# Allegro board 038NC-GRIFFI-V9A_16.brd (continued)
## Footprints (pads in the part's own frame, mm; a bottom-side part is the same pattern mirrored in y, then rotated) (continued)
PG_LTXDX_F_X1_HDVI_SL10_V3
  round 0.051 hole 2.489x2.21 unplated: (12.055,-220.342)
  round 0.508 hole 3.2 unplated: (13.055,-154.842)
  rect 1.016x1.016 hole 0.559: A1(17.684,-218.796)
  round 1.016 hole 0.559: A2(18.809,-217.796) A3(17.684,-216.796) A4(18.809,-215.796) A5(17.684,-214.796) A6(18.809,-213.796) A7(17.684,-212.796) A8(18.809,-211.796) A9(17.684,-210.796) A10(18.809,-209.796) A11(17.684,-208.796) A12(18.809,-207.796) A13(17.684,-206.796) A14(18.809,-205.796) A15(17.684,-204.796) A16(18.809,-203.796) A17(17.684,-202.796) A18(18.809,-201.796) A19(17.684,-200.796) A20(18.809,-199.796) A21(17.684,-198.796) A22(18.809,-197.796) A23(17.684,-196.796) A24(18.809,-195.796) A25(17.684,-194.796) A26(18.809,-193.796) A27(17.684,-192.796) A28(18.809,-191.796) A29(17.684,-190.796) A30(18.809,-189.796) A31(17.684,-188.796) A32(18.809,-187.796) A33(17.684,-186.796) A34(18.809,-185.796) A35(17.684,-184.796) A36(18.809,-183.796) A37(17.684,-182.796) A38(18.809,-181.796) A39(17.684,-180.796) A40(18.809,-179.796) A41(17.684,-178.796) A42(18.809,-177.796) A43(17.684,-176.796) A44(18.809,-175.796) A45(17.684,-174.796) A46(18.809,-173.796) A47(17.684,-172.796) A48(18.809,-171.796) A49(17.684,-170.796) A50(18.809,-169.796) A51(17.684,-168.796) A52(18.809,-167.796) A53(17.684,-166.796) A54(18.809,-165.796) A55(17.684,-164.796) A56(18.809,-163.796) A57(17.684,-162.796) A58(18.809,-161.796) A59(17.684,-160.796) A60(18.809,-159.796) A61(17.684,-158.796) B1(15.435,-218.796) B2(16.56,-217.796) B3(15.435,-216.796) B4(16.56,-215.796) B5(15.435,-214.796) B6(16.56,-213.796) B7(15.435,-212.796) B8(16.56,-211.796) B9(15.435,-210.796) B10(16.56,-209.796) B11(15.435,-208.796) B12(16.56,-207.796) B13(15.435,-206.796) B14(16.56,-205.796) B15(15.435,-204.796) B16(16.56,-203.796) B17(15.435,-202.796) B18(16.56,-201.796) B19(15.435,-200.796) B20(16.56,-199.796) B21(15.435,-198.796) B22(16.56,-197.796) B23(15.435,-196.796) B24(16.56,-195.796) B25(15.435,-194.796) B26(16.56,-193.796) B27(15.435,-192.796) B28(16.56,-191.796) B29(15.435,-190.796) B30(16.56,-189.796) B31(15.435,-188.796) B32(16.56,-187.796) B33(15.435,-186.796) B34(16.56,-185.796) B35(15.435,-184.796) B36(16.56,-183.796) B37(15.435,-182.796) B38(16.56,-181.796) B39(15.435,-180.796) B40(16.56,-179.796) B41(15.435,-178.796) B42(16.56,-177.796) B43(15.435,-176.796) B44(16.56,-175.796) B45(15.435,-174.796) B46(16.56,-173.796) B47(15.435,-172.796) B48(16.56,-171.796) B49(15.435,-170.796) B50(16.56,-169.796) B51(15.435,-168.796) B52(16.56,-167.796) B53(15.435,-166.796) B54(16.56,-165.796) B55(15.435,-164.796) B56(16.56,-163.796) B57(15.435,-162.796) B58(16.56,-161.796) B59(15.435,-160.796) B60(16.56,-159.796) B61(15.435,-158.796) B62(16.56,-157.796) C1(13.184,-218.796) C2(14.31,-217.796) C3(13.184,-216.796) C4(14.31,-215.796) C5(13.184,-214.796) C6(14.31,-213.796) C7(13.184,-212.796) C8(14.31,-211.796) C9(13.184,-210.796) C10(14.31,-209.796) C11(13.184,-208.796) C12(14.31,-207.796) C13(13.184,-206.796) C14(14.31,-205.796) C15(13.184,-204.796) C16(14.31,-203.796) C17(13.184,-202.796) C18(14.31,-201.796) C19(13.184,-200.796) C20(14.31,-199.796) C21(13.184,-198.796) C22(14.31,-197.796) C23(13.184,-196.796) C24(14.31,-195.796) C25(13.184,-194.796) C26(14.31,-193.796) C27(13.184,-192.796) C28(14.31,-191.796) C29(13.184,-190.796) C30(14.31,-189.796) C31(13.184,-188.796) C32(14.31,-187.796) C33(13.184,-186.796) C34(14.31,-185.796) C35(13.184,-184.796) C36(14.31,-183.796) C37(13.184,-182.796) C38(14.31,-181.796) C39(13.184,-180.796) C40(14.31,-179.796) C41(13.184,-178.796) C42(14.31,-177.796) C43(13.184,-176.796) C44(14.31,-175.796) C45(13.184,-174.796) C46(14.31,-173.796) C47(13.184,-172.796) C48(14.31,-171.796) C49(13.184,-170.796) C50(14.31,-169.796) C51(13.184,-168.796) C52(14.31,-167.796) C53(13.184,-166.796) C54(14.31,-165.796) C55(13.184,-164.796) C56(14.31,-163.796) C57(13.184,-162.796) C58(14.31,-161.796) C59(13.184,-160.796) C60(14.31,-159.796) C61(13.184,-158.796) C62(14.31,-157.796) D1(10.934,-218.796) D2(12.059,-217.796) D3(10.934,-216.796) D4(12.059,-215.796) D5(10.934,-214.796) D6(12.059,-213.796) D7(10.934,-212.796) D8(12.059,-211.796) D9(10.934,-210.796) D10(12.059,-209.796) D11(10.934,-208.796) D12(12.059,-207.796) D13(10.934,-206.796) D14(12.059,-205.796) D15(10.934,-204.796) D16(12.059,-203.796) D17(10.934,-202.796) D18(12.059,-201.796) D19(10.934,-200.796) D20(12.059,-199.796) D21(10.934,-198.796) D22(12.059,-197.796) D23(10.934,-196.796) D24(12.059,-195.796) D25(10.934,-194.796) D26(12.059,-193.796) D27(10.934,-192.796) D28(12.059,-191.796) D29(10.934,-190.796) D30(12.059,-189.796) D31(10.934,-188.796) D32(12.059,-187.796) D33(10.934,-186.796) D34(12.059,-185.796) D35(10.934,-184.796) D36(12.059,-183.796) D37(10.934,-182.796) D38(12.059,-181.796) D39(10.934,-180.796) D40(12.059,-179.796) D41(10.934,-178.796) D42(12.059,-177.796) D43(10.934,-176.796) D44(12.059,-175.796) D45(10.934,-174.796) D46(12.059,-173.796) D47(10.934,-172.796) D48(12.059,-171.796) D49(10.934,-170.796) D50(12.059,-169.796) D51(10.934,-168.796) D52(12.059,-167.796) D53(10.934,-166.796) D54(12.059,-165.796) D55(10.934,-164.796) D56(12.059,-163.796) D57(10.934,-162.796) D58(12.059,-161.796) D59(10.934,-160.796) D60(12.059,-159.796) D61(10.934,-158.796) E1(8.685,-218.796) E2(9.809,-217.796) E3(8.685,-216.796) E4(9.809,-215.796) E5(8.685,-214.796) E6(9.809,-213.796) E7(8.685,-212.796) E8(9.809,-211.796) E9(8.685,-210.796) E10(9.809,-209.796) E11(8.685,-208.796) E12(9.809,-207.796) E13(8.685,-206.796) E14(9.809,-205.796) E15(8.685,-204.796) E16(9.809,-203.796) E17(8.685,-202.796) E18(9.809,-201.796) E19(8.685,-200.796) E20(9.809,-199.796) E21(8.685,-198.796) E22(9.809,-197.796) E23(8.685,-196.796) E24(9.809,-195.796) E25(8.685,-194.796) E26(9.809,-193.796) E27(8.685,-192.796) E28(9.809,-191.796) E29(8.685,-190.796) E30(9.809,-189.796) E31(8.685,-188.796) E32(9.809,-187.796) E33(8.685,-186.796) E34(9.809,-185.796) E35(8.685,-184.796) E36(9.809,-183.796) E37(8.685,-182.796) E38(9.809,-181.796) E39(8.685,-180.796) E40(9.809,-179.796) E41(8.685,-178.796) E42(9.809,-177.796) E43(8.685,-176.796) E44(9.809,-175.796) E45(8.685,-174.796) E46(9.809,-173.796) E47(8.685,-172.796) E48(9.809,-171.796) E49(8.685,-170.796) E50(9.809,-169.796) E51(8.685,-168.796) E52(9.809,-167.796) E53(8.685,-166.796) E54(9.809,-165.796) E55(8.685,-164.796) E56(9.809,-163.796) E57(8.685,-162.796) E58(9.809,-161.796) E59(8.685,-160.796) E60(9.809,-159.796) E61(8.685,-158.796) E62(9.809,-157.796) F1(6.435,-218.796) F2(7.56,-217.796) F3(6.435,-216.796) F4(7.56,-215.796) F5(6.435,-214.796) F6(7.56,-213.796) F7(6.435,-212.796) F8(7.56,-211.796) F9(6.435,-210.796) F10(7.56,-209.796) F11(6.435,-208.796) F12(7.56,-207.796) F13(6.435,-206.796) F14(7.56,-205.796) F15(6.435,-204.796) F16(7.56,-203.796) F17(6.435,-202.796) F18(7.56,-201.796) F19(6.435,-200.796) F20(7.56,-199.796) F21(6.435,-198.796) F22(7.56,-197.796) F23(6.435,-196.796) F24(7.56,-195.796) F25(6.435,-194.796) F26(7.56,-193.796) F27(6.435,-192.796) F28(7.56,-191.796) F29(6.435,-190.796) F30(7.56,-189.796) F31(6.435,-188.796) F32(7.56,-187.796) F33(6.435,-186.796) F34(7.56,-185.796) F35(6.435,-184.796) F36(7.56,-183.796) F37(6.435,-182.796) F38(7.56,-181.796) F39(6.435,-180.796) F40(7.56,-179.796) F41(6.435,-178.796) F42(7.56,-177.796) F43(6.435,-176.796) F44(7.56,-175.796) F45(6.435,-174.796) F46(7.56,-173.796) F47(6.435,-172.796) F48(7.56,-171.796) F49(6.435,-170.796) F50(7.56,-169.796) F51(6.435,-168.796) F52(7.56,-167.796) F53(6.435,-166.796) F54(7.56,-165.796) F55(6.435,-164.796) F56(7.56,-163.796) F57(6.435,-162.796) F58(7.56,-161.796) F59(6.435,-160.796) F60(7.56,-159.796) F61(6.435,-158.796) F62(7.56,-157.796) G2(5.31,-217.796) G4(5.31,-215.796) G6(5.31,-213.796) G8(5.31,-211.796) G10(5.31,-209.796) G12(5.31,-207.796) G14(5.31,-205.796) G16(5.31,-203.796) G18(5.31,-201.796) G20(5.31,-199.796) G22(5.31,-197.796) G24(5.31,-195.796) G26(5.31,-193.796) G28(5.31,-191.796) G30(5.31,-189.796) G32(5.31,-187.796) G34(5.31,-185.796) G36(5.31,-183.796) G38(5.31,-181.796) G40(5.31,-179.796) G42(5.31,-177.796) G44(5.31,-175.796) G46(5.31,-173.796) G48(5.31,-171.796) G50(5.31,-169.796) G52(5.31,-167.796) G54(5.31,-165.796) G56(5.31,-163.796) G58(5.31,-161.796) G60(5.31,-159.796)
  custom 0.257x0.257 smd: Z5(19.934,-214.796) Z7(19.934,-212.796) Z9(19.934,-210.796) Z11(19.934,-208.796) Z13(19.934,-206.796) Z15(19.934,-204.796) Z17(19.934,-202.796) Z19(19.934,-200.796) Z21(19.934,-198.796) Z23(19.934,-196.796) Z25(19.934,-194.796) Z27(19.934,-192.796) Z29(19.934,-190.796) Z31(19.934,-188.796) Z33(19.934,-186.796) Z35(19.934,-184.796) Z37(19.934,-182.796) Z39(19.934,-180.796) Z41(19.934,-178.796) Z43(19.934,-176.796) Z45(19.934,-174.796) Z47(19.934,-172.796) Z49(19.934,-170.796) Z51(19.934,-168.796) Z53(19.934,-166.796) Z55(19.934,-164.796) Z57(19.934,-162.796) Z59(19.934,-160.796) Z61(19.934,-158.796)
PG_LTXDX_F_X1_HDVI_SL13_V3
  round 0.508 hole 3.2 unplated: (35.206,154.842)
  round 0.051 hole 2.489x2.21 unplated: (36.205,220.342)
  rect 1.016x1.016 hole 0.559: A1(30.576,218.796)
  round 1.016 hole 0.559: A2(29.451,217.796) A3(30.576,216.796) A4(29.451,215.796) A5(30.576,214.796) A6(29.451,213.796) A7(30.576,212.796) A8(29.451,211.796) A9(30.576,210.796) A10(29.451,209.796) A11(30.576,208.796) A12(29.451,207.796) A13(30.576,206.796) A14(29.451,205.796) A15(30.576,204.796) A16(29.451,203.796) A17(30.576,202.796) A18(29.451,201.796) A19(30.576,200.796) A20(29.451,199.796) A21(30.576,198.796) A22(29.451,197.796) A23(30.576,196.796) A24(29.451,195.796) A25(30.576,194.796) A26(29.451,193.796) A27(30.576,192.796) A28(29.451,191.796) A29(30.576,190.796) A30(29.451,189.796) A31(30.576,188.796) A32(29.451,187.796) A33(30.576,186.796) A34(29.451,185.796) A35(30.576,184.796) A36(29.451,183.796) A37(30.576,182.796) A38(29.451,181.796) A39(30.576,180.796) A40(29.451,179.796) A41(30.576,178.796) A42(29.451,177.796) A43(30.576,176.796) A44(29.451,175.796) A45(30.576,174.796) A46(29.451,173.796) A47(30.576,172.796) A48(29.451,171.796) A49(30.576,170.796) A50(29.451,169.796) A51(30.576,168.796) A52(29.451,167.796) A53(30.576,166.796) A54(29.451,165.796) A55(30.576,164.796) A56(29.451,163.796) A57(30.576,162.796) A58(29.451,161.796) A59(30.576,160.796) A60(29.451,159.796) A61(30.576,158.796) B1(32.825,218.796) B2(31.7,217.796) B3(32.825,216.796) B4(31.7,215.796) B5(32.825,214.796) B6(31.7,213.796) B7(32.825,212.796) B8(31.7,211.796) B9(32.825,210.796) B10(31.7,209.796) B11(32.825,208.796) B12(31.7,207.796) B13(32.825,206.796) B14(31.7,205.796) B15(32.825,204.796) B16(31.7,203.796) B17(32.825,202.796) B18(31.7,201.796) B19(32.825,200.796) B20(31.7,199.796) B21(32.825,198.796) B22(31.7,197.796) B23(32.825,196.796) B24(31.7,195.796) B25(32.825,194.796) B26(31.7,193.796) B27(32.825,192.796) B28(31.7,191.796) B29(32.825,190.796) B30(31.7,189.796) B31(32.825,188.796) B32(31.7,187.796) B33(32.825,186.796) B34(31.7,185.796) B35(32.825,184.796) B36(31.7,183.796) B37(32.825,182.796) B38(31.7,181.796) B39(32.825,180.796) B40(31.7,179.796) B41(32.825,178.796) B42(31.7,177.796) B43(32.825,176.796) B44(31.7,175.796) B45(32.825,174.796) B46(31.7,173.796) B47(32.825,172.796) B48(31.7,171.796) B49(32.825,170.796) B50(31.7,169.796) B51(32.825,168.796) B52(31.7,167.796) B53(32.825,166.796) B54(31.7,165.796) B55(32.825,164.796) B56(31.7,163.796) B57(32.825,162.796) B58(31.7,161.796) B59(32.825,160.796) B60(31.7,159.796) B61(32.825,158.796) B62(31.7,157.796) C1(35.076,218.796) C2(33.95,217.796) C3(35.076,216.796) C4(33.95,215.796) C5(35.076,214.796) C6(33.95,213.796) C7(35.076,212.796) C8(33.95,211.796) C9(35.076,210.796) C10(33.95,209.796) C11(35.076,208.796) C12(33.95,207.796) C13(35.076,206.796) C14(33.95,205.796) C15(35.076,204.796) C16(33.95,203.796) C17(35.076,202.796) C18(33.95,201.796) C19(35.076,200.796) C20(33.95,199.796) C21(35.076,198.796) C22(33.95,197.796) C23(35.076,196.796) C24(33.95,195.796) C25(35.076,194.796) C26(33.95,193.796) C27(35.076,192.796) C28(33.95,191.796) C29(35.076,190.796) C30(33.95,189.796) C31(35.076,188.796) C32(33.95,187.796) C33(35.076,186.796) C34(33.95,185.796) C35(35.076,184.796) C36(33.95,183.796) C37(35.076,182.796) C38(33.95,181.796) C39(35.076,180.796) C40(33.95,179.796) C41(35.076,178.796) C42(33.95,177.796) C43(35.076,176.796) C44(33.95,175.796) C45(35.076,174.796) C46(33.95,173.796) C47(35.076,172.796) C48(33.95,171.796) C49(35.076,170.796) C50(33.95,169.796) C51(35.076,168.796) C52(33.95,167.796) C53(35.076,166.796) C54(33.95,165.796) C55(35.076,164.796) C56(33.95,163.796) C57(35.076,162.796) C58(33.95,161.796) C59(35.076,160.796) C60(33.95,159.796) C61(35.076,158.796) C62(33.95,157.796) D1(37.326,218.796) D2(36.201,217.796) D3(37.326,216.796) D4(36.201,215.796) D5(37.326,214.796) D6(36.201,213.796) D7(37.326,212.796) D8(36.201,211.796) D9(37.326,210.796) D10(36.201,209.796) D11(37.326,208.796) D12(36.201,207.796) D13(37.326,206.796) D14(36.201,205.796) D15(37.326,204.796) D16(36.201,203.796) D17(37.326,202.796) D18(36.201,201.796) D19(37.326,200.796) D20(36.201,199.796) D21(37.326,198.796) D22(36.201,197.796) D23(37.326,196.796) D24(36.201,195.796) D25(37.326,194.796) D26(36.201,193.796) D27(37.326,192.796) D28(36.201,191.796) D29(37.326,190.796) D30(36.201,189.796) D31(37.326,188.796) D32(36.201,187.796) D33(37.326,186.796) D34(36.201,185.796) D35(37.326,184.796) D36(36.201,183.796) D37(37.326,182.796) D38(36.201,181.796) D39(37.326,180.796) D40(36.201,179.796) D41(37.326,178.796) D42(36.201,177.796) D43(37.326,176.796) D44(36.201,175.796) D45(37.326,174.796) D46(36.201,173.796) D47(37.326,172.796) D48(36.201,171.796) D49(37.326,170.796) D50(36.201,169.796) D51(37.326,168.796) D52(36.201,167.796) D53(37.326,166.796) D54(36.201,165.796) D55(37.326,164.796) D56(36.201,163.796) D57(37.326,162.796) D58(36.201,161.796) D59(37.326,160.796) D60(36.201,159.796) D61(37.326,158.796) E1(39.575,218.796) E2(38.451,217.796) E3(39.575,216.796) E4(38.451,215.796) E5(39.575,214.796) E6(38.451,213.796) E7(39.575,212.796) E8(38.451,211.796) E9(39.575,210.796) E10(38.451,209.796) E11(39.575,208.796) E12(38.451,207.796) E13(39.575,206.796) E14(38.451,205.796) E15(39.575,204.796) E16(38.451,203.796) E17(39.575,202.796) E18(38.451,201.796) E19(39.575,200.796) E20(38.451,199.796) E21(39.575,198.796) E22(38.451,197.796) E23(39.575,196.796) E24(38.451,195.796) E25(39.575,194.796) E26(38.451,193.796) E27(39.575,192.796) E28(38.451,191.796) E29(39.575,190.796) E30(38.451,189.796) E31(39.575,188.796) E32(38.451,187.796) E33(39.575,186.796) E34(38.451,185.796) E35(39.575,184.796) E36(38.451,183.796) E37(39.575,182.796) E38(38.451,181.796) E39(39.575,180.796) E40(38.451,179.796) E41(39.575,178.796) E42(38.451,177.796) E43(39.575,176.796) E44(38.451,175.796) E45(39.575,174.796) E46(38.451,173.796) E47(39.575,172.796) E48(38.451,171.796) E49(39.575,170.796) E50(38.451,169.796) E51(39.575,168.796) E52(38.451,167.796) E53(39.575,166.796) E54(38.451,165.796) E55(39.575,164.796) E56(38.451,163.796) E57(39.575,162.796) E58(38.451,161.796) E59(39.575,160.796) E60(38.451,159.796) E61(39.575,158.796) E62(38.451,157.796) F1(41.825,218.796) F2(40.7,217.796) F3(41.825,216.796) F4(40.7,215.796) F5(41.825,214.796) F6(40.7,213.796) F7(41.825,212.796) F8(40.7,211.796) F9(41.825,210.796) F10(40.7,209.796) F11(41.825,208.796) F12(40.7,207.796) F13(41.825,206.796) F14(40.7,205.796) F15(41.825,204.796) F16(40.7,203.796) F17(41.825,202.796) F18(40.7,201.796) F19(41.825,200.796) F20(40.7,199.796) F21(41.825,198.796) F22(40.7,197.796) F23(41.825,196.796) F24(40.7,195.796) F25(41.825,194.796) F26(40.7,193.796) F27(41.825,192.796) F28(40.7,191.796) F29(41.825,190.796) F30(40.7,189.796) F31(41.825,188.796) F32(40.7,187.796) F33(41.825,186.796) F34(40.7,185.796) F35(41.825,184.796) F36(40.7,183.796) F37(41.825,182.796) F38(40.7,181.796) F39(41.825,180.796) F40(40.7,179.796) F41(41.825,178.796) F42(40.7,177.796) F43(41.825,176.796) F44(40.7,175.796) F45(41.825,174.796) F46(40.7,173.796) F47(41.825,172.796) F48(40.7,171.796) F49(41.825,170.796) F50(40.7,169.796) F51(41.825,168.796) F52(40.7,167.796) F53(41.825,166.796) F54(40.7,165.796) F55(41.825,164.796) F56(40.7,163.796) F57(41.825,162.796) F58(40.7,161.796) F59(41.825,160.796) F60(40.7,159.796) F61(41.825,158.796) F62(40.7,157.796) G2(42.95,217.796) G4(42.95,215.796) G6(42.95,213.796) G8(42.95,211.796) G10(42.95,209.796) G12(42.95,207.796) G14(42.95,205.796) G16(42.95,203.796) G18(42.95,201.796) G20(42.95,199.796) G22(42.95,197.796) G24(42.95,195.796) G26(42.95,193.796) G28(42.95,191.796) G30(42.95,189.796) G32(42.95,187.796) G34(42.95,185.796) G36(42.95,183.796) G38(42.95,181.796) G40(42.95,179.796) G42(42.95,177.796) G44(42.95,175.796) G46(42.95,173.796) G48(42.95,171.796) G50(42.95,169.796) G52(42.95,167.796) G54(42.95,165.796) G56(42.95,163.796) G58(42.95,161.796) G60(42.95,159.796)
  custom 0.257x0.257 smd: Z5(28.326,214.796) Z7(28.326,212.796) Z9(28.326,210.796) Z11(28.326,208.796) Z13(28.326,206.796) Z15(28.326,204.796) Z17(28.326,202.796) Z19(28.326,200.796) Z21(28.326,198.796) Z23(28.326,196.796) Z25(28.326,194.796) Z27(28.326,192.796) Z29(28.326,190.796) Z31(28.326,188.796) Z33(28.326,186.796) Z35(28.326,184.796) Z37(28.326,182.796) Z39(28.326,180.796) Z41(28.326,178.796) Z43(28.326,176.796) Z45(28.326,174.796) Z47(28.326,172.796) Z49(28.326,170.796) Z51(28.326,168.796) Z53(28.326,166.796) Z55(28.326,164.796) Z57(28.326,162.796) Z59(28.326,160.796) Z61(28.326,158.796)
PG_LTXDX_F_X1_OUTLINE_FULL_V2
  round 0.508 hole 7.925 unplated: (-139.7,145.034)
  round 0.508 hole 11.125 unplated: (-139.7,-145.034) (139.7,145.034) (139.7,-145.034)
  round 0.508 hole 3.099 unplated: (-130.048,229.87)
  round 0.508 hole 3.404 unplated: (-130.048,-229.87)
  round 0.508 hole 4.674 unplated: (-128.27,187.325) (-128.27,60.325) (-128.27,-60.325) (-128.27,-187.325) (-120.65,229.87) (-120.65,144.78) (-120.65,-144.78) (-120.65,-229.87) (-72.39,229.87) (-72.39,144.78) (-72.39,-144.78) (-72.39,-229.87) (-24.13,229.87) (-24.13,144.78) (-24.13,-144.78) (-24.13,-229.87) (24.13,229.87) (24.13,144.78) (24.13,-144.78) (24.13,-229.87) (72.39,229.87) (72.39,144.78) (72.39,-144.78) (72.39,-229.87) (120.65,229.87) (120.65,144.78) (120.65,-144.78) (120.65,-229.87) (128.27,187.325) (128.27,60.325) (128.27,-60.325) (128.27,-187.325)
  round 0.508 hole 4.572x3.099 unplated: (130.048,229.87)
PG_LTXDX_F_X1_PG400ND_SL01_V3
  round 0.508 hole 3.2 unplated: (-109.574,154.842)
  round 0.051 hole 2.489x2.21 unplated: (-108.574,220.342)
  rect 1.016x1.016 smd: A1(-114.204,218.796)
  round 1.016 smd: A2(-115.329,217.796) A3(-114.204,216.796) A4(-115.329,215.796) B1(-111.955,218.796) B2(-113.08,217.796) B3(-111.955,216.796) B4(-113.08,215.796) B62(-113.08,157.796) C1(-109.704,218.796) C2(-110.83,217.796) C3(-109.704,216.796) C4(-110.83,215.796) C62(-110.83,157.796) D1(-107.454,218.796) D2(-108.579,217.796) D3(-107.454,216.796) D4(-108.579,215.796) E1(-105.205,218.796) E2(-106.329,217.796) E3(-105.205,216.796) E4(-106.329,215.796) E62(-106.329,157.796) F1(-102.955,218.796) F2(-104.08,217.796) F3(-102.955,216.796) F4(-104.08,215.796) F62(-104.08,157.796) G2(-101.83,217.796) G4(-101.83,215.796) G6(-101.83,213.796) G8(-101.83,211.796) G10(-101.83,209.796) G12(-101.83,207.796) G14(-101.83,205.796) G16(-101.83,203.796) G18(-101.83,201.796) G20(-101.83,199.796) G22(-101.83,197.796) G24(-101.83,195.796) G26(-101.83,193.796) G28(-101.83,191.796) G30(-101.83,189.796) G32(-101.83,187.796) G34(-101.83,185.796) G36(-101.83,183.796) G38(-101.83,181.796) G40(-101.83,179.796) G42(-101.83,177.796) G44(-101.83,175.796) G46(-101.83,173.796) G48(-101.83,171.796) G50(-101.83,169.796) G52(-101.83,167.796) G54(-101.83,165.796) G56(-101.83,163.796) G58(-101.83,161.796) G60(-101.83,159.796)
  custom 0.257x0.257 smd: A5(-114.204,214.796) A6(-115.329,213.796) A7(-114.204,212.796) A8(-115.329,211.796) A9(-114.204,210.796) A10(-115.329,209.796) A11(-114.204,208.796) A12(-115.329,207.796) A13(-114.204,206.796) A14(-115.329,205.796) A15(-114.204,204.796) A16(-115.329,203.796) A17(-114.204,202.796) A18(-115.329,201.796) A19(-114.204,200.796) A20(-115.329,199.796) A21(-114.204,198.796) A22(-115.329,197.796) A23(-114.204,196.796) A24(-115.329,195.796) A25(-114.204,194.796) A26(-115.329,193.796) A27(-114.204,192.796) A28(-115.329,191.796) A29(-114.204,190.796) A30(-115.329,189.796) A31(-114.204,188.796) A32(-115.329,187.796) A33(-114.204,186.796) A34(-115.329,185.796) A35(-114.204,184.796) A36(-115.329,183.796) A37(-114.204,182.796) A38(-115.329,181.796) A39(-114.204,180.796) A40(-115.329,179.796) A41(-114.204,178.796) A42(-115.329,177.796) A43(-114.204,176.796) A44(-115.329,175.796) A45(-114.204,174.796) A46(-115.329,173.796) A47(-114.204,172.796) A48(-115.329,171.796) A49(-114.204,170.796) A50(-115.329,169.796) A51(-114.204,168.796) A52(-115.329,167.796) A53(-114.204,166.796) A54(-115.329,165.796) A55(-114.204,164.796) A56(-115.329,163.796) A57(-114.204,162.796) A58(-115.329,161.796) A59(-114.204,160.796) A60(-115.329,159.796) A61(-114.204,158.796) B5(-111.955,214.796) B6(-113.08,213.796) B7(-111.955,212.796) B8(-113.08,211.796) B9(-111.955,210.796) B10(-113.08,209.796) B11(-111.955,208.796) B12(-113.08,207.796) B13(-111.955,206.796) B14(-113.08,205.796) B15(-111.955,204.796) B16(-113.08,203.796) B17(-111.955,202.796) B18(-113.08,201.796) B19(-111.955,200.796) B20(-113.08,199.796) B21(-111.955,198.796) B22(-113.08,197.796) B23(-111.955,196.796) B24(-113.08,195.796) B25(-111.955,194.796) B26(-113.08,193.796) B27(-111.955,192.796) B28(-113.08,191.796) B29(-111.955,190.796) B30(-113.08,189.796) B31(-111.955,188.796) B32(-113.08,187.796) B33(-111.955,186.796) B34(-113.08,185.796) B35(-111.955,184.796) B36(-113.08,183.796) B37(-111.955,182.796) B38(-113.08,181.796) B39(-111.955,180.796) B40(-113.08,179.796) B41(-111.955,178.796) B42(-113.08,177.796) B43(-111.955,176.796) B44(-113.08,175.796) B45(-111.955,174.796) B46(-113.08,173.796) B47(-111.955,172.796) B48(-113.08,171.796) B49(-111.955,170.796) B50(-113.08,169.796) B51(-111.955,168.796) B52(-113.08,167.796) B53(-111.955,166.796) B54(-113.08,165.796) B55(-111.955,164.796) B56(-113.08,163.796) B57(-111.955,162.796) B58(-113.08,161.796) B59(-111.955,160.796) B60(-113.08,159.796) B61(-111.955,158.796) C5(-109.704,214.796) C6(-110.83,213.796) C7(-109.704,212.796) C8(-110.83,211.796) C9(-109.704,210.796) C10(-110.83,209.796) C11(-109.704,208.796) C12(-110.83,207.796) C13(-109.704,206.796) C14(-110.83,205.796) C15(-109.704,204.796) C16(-110.83,203.796) C17(-109.704,202.796) C18(-110.83,201.796) C19(-109.704,200.796) C20(-110.83,199.796) C21(-109.704,198.796) C22(-110.83,197.796) C23(-109.704,196.796) C24(-110.83,195.796) C25(-109.704,194.796) C26(-110.83,193.796) C27(-109.704,192.796) C28(-110.83,191.796) C29(-109.704,190.796) C30(-110.83,189.796) C31(-109.704,188.796) C32(-110.83,187.796) C33(-109.704,186.796) C34(-110.83,185.796) C35(-109.704,184.796) C36(-110.83,183.796) C37(-109.704,182.796) C38(-110.83,181.796) C39(-109.704,180.796) C40(-110.83,179.796) C41(-109.704,178.796) C42(-110.83,177.796) C43(-109.704,176.796) C44(-110.83,175.796) C45(-109.704,174.796) C46(-110.83,173.796) C47(-109.704,172.796) C48(-110.83,171.796) C49(-109.704,170.796) C50(-110.83,169.796) C51(-109.704,168.796) C52(-110.83,167.796) C53(-109.704,166.796) C54(-110.83,165.796) C55(-109.704,164.796) C56(-110.83,163.796) C57(-109.704,162.796) C58(-110.83,161.796) C59(-109.704,160.796) C60(-110.83,159.796) C61(-109.704,158.796) D5(-107.454,214.796) D6(-108.579,213.796) D7(-107.454,212.796) D8(-108.579,211.796) D9(-107.454,210.796) D10(-108.579,209.796) D11(-107.454,208.796) D12(-108.579,207.796) D13(-107.454,206.796) D14(-108.579,205.796) D15(-107.454,204.796) D16(-108.579,203.796) D17(-107.454,202.796) D18(-108.579,201.796) D19(-107.454,200.796) D20(-108.579,199.796) D21(-107.454,198.796) D22(-108.579,197.796) D23(-107.454,196.796) D24(-108.579,195.796) D25(-107.454,194.796) D26(-108.579,193.796) D27(-107.454,192.796) D28(-108.579,191.796) D29(-107.454,190.796) D30(-108.579,189.796) D31(-107.454,188.796) D32(-108.579,187.796) D33(-107.454,186.796) D34(-108.579,185.796) D35(-107.454,184.796) D36(-108.579,183.796) D37(-107.454,182.796) D38(-108.579,181.796) D39(-107.454,180.796) D40(-108.579,179.796) D41(-107.454,178.796) D42(-108.579,177.796) D43(-107.454,176.796) D44(-108.579,175.796) D45(-107.454,174.796) D46(-108.579,173.796) D47(-107.454,172.796) D48(-108.579,171.796) D49(-107.454,170.796) D50(-108.579,169.796) D51(-107.454,168.796) D52(-108.579,167.796) D53(-107.454,166.796) D54(-108.579,165.796) D55(-107.454,164.796) D56(-108.579,163.796) D57(-107.454,162.796) D58(-108.579,161.796) D59(-107.454,160.796) D60(-108.579,159.796) D61(-107.454,158.796) E5(-105.205,214.796) E6(-106.329,213.796) E7(-105.205,212.796) E8(-106.329,211.796) E9(-105.205,210.796) E10(-106.329,209.796) E11(-105.205,208.796) E12(-106.329,207.796) E13(-105.205,206.796) E14(-106.329,205.796) E15(-105.205,204.796) E16(-106.329,203.796) E17(-105.205,202.796) E18(-106.329,201.796) E19(-105.205,200.796) E20(-106.329,199.796) E21(-105.205,198.796) E22(-106.329,197.796) E23(-105.205,196.796) E24(-106.329,195.796) E25(-105.205,194.796) E26(-106.329,193.796) E27(-105.205,192.796) E28(-106.329,191.796) E29(-105.205,190.796) E30(-106.329,189.796) E31(-105.205,188.796) E32(-106.329,187.796) E33(-105.205,186.796) E34(-106.329,185.796) E35(-105.205,184.796) E36(-106.329,183.796) E37(-105.205,182.796) E38(-106.329,181.796) E39(-105.205,180.796) E40(-106.329,179.796) E41(-105.205,178.796) E42(-106.329,177.796) E43(-105.205,176.796) E44(-106.329,175.796) E45(-105.205,174.796) E46(-106.329,173.796) E47(-105.205,172.796) E48(-106.329,171.796) E49(-105.205,170.796) E50(-106.329,169.796) E51(-105.205,168.796) E52(-106.329,167.796) E53(-105.205,166.796) E54(-106.329,165.796) E55(-105.205,164.796) E56(-106.329,163.796) E57(-105.205,162.796) E58(-106.329,161.796) E59(-105.205,160.796) E60(-106.329,159.796) E61(-105.205,158.796) F5(-102.955,214.796) F6(-104.08,213.796) F7(-102.955,212.796) F8(-104.08,211.796) F9(-102.955,210.796) F10(-104.08,209.796) F11(-102.955,208.796) F12(-104.08,207.796) F13(-102.955,206.796) F14(-104.08,205.796) F15(-102.955,204.796) F16(-104.08,203.796) F17(-102.955,202.796) F18(-104.08,201.796) F19(-102.955,200.796) F20(-104.08,199.796) F21(-102.955,198.796) F22(-104.08,197.796) F23(-102.955,196.796) F24(-104.08,195.796) F25(-102.955,194.796) F26(-104.08,193.796) F27(-102.955,192.796) F28(-104.08,191.796) F29(-102.955,190.796) F30(-104.08,189.796) F31(-102.955,188.796) F32(-104.08,187.796) F33(-102.955,186.796) F34(-104.08,185.796) F35(-102.955,184.796) F36(-104.08,183.796) F37(-102.955,182.796) F38(-104.08,181.796) F39(-102.955,180.796) F40(-104.08,179.796) F41(-102.955,178.796) F42(-104.08,177.796) F43(-102.955,176.796) F44(-104.08,175.796) F45(-102.955,174.796) F46(-104.08,173.796) F47(-102.955,172.796) F48(-104.08,171.796) F49(-102.955,170.796) F50(-104.08,169.796) F51(-102.955,168.796) F52(-104.08,167.796) F53(-102.955,166.796) F54(-104.08,165.796) F55(-102.955,164.796) F56(-104.08,163.796) F57(-102.955,162.796) F58(-104.08,161.796) F59(-102.955,160.796) F60(-104.08,159.796) F61(-102.955,158.796) Z5(-116.454,214.796) Z7(-116.454,212.796) Z9(-116.454,210.796) Z11(-116.454,208.796) Z13(-116.454,206.796) Z15(-116.454,204.796) Z17(-116.454,202.796) Z19(-116.454,200.796) Z21(-116.454,198.796) Z23(-116.454,196.796) Z25(-116.454,194.796) Z27(-116.454,192.796) Z29(-116.454,190.796) Z31(-116.454,188.796) Z33(-116.454,186.796) Z35(-116.454,184.796) Z37(-116.454,182.796) Z39(-116.454,180.796) Z41(-116.454,178.796) Z43(-116.454,176.796) Z45(-116.454,174.796) Z47(-116.454,172.796) Z49(-116.454,170.796) Z51(-116.454,168.796) Z53(-116.454,166.796) Z55(-116.454,164.796) Z57(-116.454,162.796) Z59(-116.454,160.796) Z61(-116.454,158.796)
PG_LTXDX_F_X1_PG400ND_SL02_V3
  round 0.051 hole 2.489x2.21 unplated: (-84.465,-220.342)
  round 0.508 hole 3.2 unplated: (-83.466,-154.842)
  rect 1.016x1.016 smd: A1(-78.836,-218.796)
  round 1.016 smd: A2(-77.711,-217.796) A3(-78.836,-216.796) A4(-77.711,-215.796) B1(-81.085,-218.796) B2(-79.96,-217.796) B3(-81.085,-216.796) B4(-79.96,-215.796) B62(-79.96,-157.796) C1(-83.336,-218.796) C2(-82.21,-217.796) C3(-83.336,-216.796) C4(-82.21,-215.796) C62(-82.21,-157.796) D1(-85.586,-218.796) D2(-84.461,-217.796) D3(-85.586,-216.796) D4(-84.461,-215.796) E1(-87.835,-218.796) E2(-86.711,-217.796) E3(-87.835,-216.796) E4(-86.711,-215.796) E62(-86.711,-157.796) F1(-90.085,-218.796) F2(-88.96,-217.796) F3(-90.085,-216.796) F4(-88.96,-215.796) F62(-88.96,-157.796) G2(-91.21,-217.796) G4(-91.21,-215.796) G6(-91.21,-213.796) G8(-91.21,-211.796) G10(-91.21,-209.796) G12(-91.21,-207.796) G14(-91.21,-205.796) G16(-91.21,-203.796) G18(-91.21,-201.796) G20(-91.21,-199.796) G22(-91.21,-197.796) G24(-91.21,-195.796) G26(-91.21,-193.796) G28(-91.21,-191.796) G30(-91.21,-189.796) G32(-91.21,-187.796) G34(-91.21,-185.796) G36(-91.21,-183.796) G38(-91.21,-181.796) G40(-91.21,-179.796) G42(-91.21,-177.796) G44(-91.21,-175.796) G46(-91.21,-173.796) G48(-91.21,-171.796) G50(-91.21,-169.796) G52(-91.21,-167.796) G54(-91.21,-165.796) G56(-91.21,-163.796) G58(-91.21,-161.796) G60(-91.21,-159.796)
  custom 0.257x0.257 smd: A5(-78.836,-214.796) A6(-77.711,-213.796) A7(-78.836,-212.796) A8(-77.711,-211.796) A9(-78.836,-210.796) A10(-77.711,-209.796) A11(-78.836,-208.796) A12(-77.711,-207.796) A13(-78.836,-206.796) A14(-77.711,-205.796) A15(-78.836,-204.796) A16(-77.711,-203.796) A17(-78.836,-202.796) A18(-77.711,-201.796) A19(-78.836,-200.796) A20(-77.711,-199.796) A21(-78.836,-198.796) A22(-77.711,-197.796) A23(-78.836,-196.796) A24(-77.711,-195.796) A25(-78.836,-194.796) A26(-77.711,-193.796) A27(-78.836,-192.796) A28(-77.711,-191.796) A29(-78.836,-190.796) A30(-77.711,-189.796) A31(-78.836,-188.796) A32(-77.711,-187.796) A33(-78.836,-186.796) A34(-77.711,-185.796) A35(-78.836,-184.796) A36(-77.711,-183.796) A37(-78.836,-182.796) A38(-77.711,-181.796) A39(-78.836,-180.796) A40(-77.711,-179.796) A41(-78.836,-178.796) A42(-77.711,-177.796) A43(-78.836,-176.796) A44(-77.711,-175.796) A45(-78.836,-174.796) A46(-77.711,-173.796) A47(-78.836,-172.796) A48(-77.711,-171.796) A49(-78.836,-170.796) A50(-77.711,-169.796) A51(-78.836,-168.796) A52(-77.711,-167.796) A53(-78.836,-166.796) A54(-77.711,-165.796) A55(-78.836,-164.796) A56(-77.711,-163.796) A57(-78.836,-162.796) A58(-77.711,-161.796) A59(-78.836,-160.796) A60(-77.711,-159.796) A61(-78.836,-158.796) B5(-81.085,-214.796) B6(-79.96,-213.796) B7(-81.085,-212.796) B8(-79.96,-211.796) B9(-81.085,-210.796) B10(-79.96,-209.796) B11(-81.085,-208.796) B12(-79.96,-207.796) B13(-81.085,-206.796) B14(-79.96,-205.796) B15(-81.085,-204.796) B16(-79.96,-203.796) B17(-81.085,-202.796) B18(-79.96,-201.796) B19(-81.085,-200.796) B20(-79.96,-199.796) B21(-81.085,-198.796) B22(-79.96,-197.796) B23(-81.085,-196.796) B24(-79.96,-195.796) B25(-81.085,-194.796) B26(-79.96,-193.796) B27(-81.085,-192.796) B28(-79.96,-191.796) B29(-81.085,-190.796) B30(-79.96,-189.796) B31(-81.085,-188.796) B32(-79.96,-187.796) B33(-81.085,-186.796) B34(-79.96,-185.796) B35(-81.085,-184.796) B36(-79.96,-183.796) B37(-81.085,-182.796) B38(-79.96,-181.796) B39(-81.085,-180.796) B40(-79.96,-179.796) B41(-81.085,-178.796) B42(-79.96,-177.796) B43(-81.085,-176.796) B44(-79.96,-175.796) B45(-81.085,-174.796) B46(-79.96,-173.796) B47(-81.085,-172.796) B48(-79.96,-171.796) B49(-81.085,-170.796) B50(-79.96,-169.796) B51(-81.085,-168.796) B52(-79.96,-167.796) B53(-81.085,-166.796) B54(-79.96,-165.796) B55(-81.085,-164.796) B56(-79.96,-163.796) B57(-81.085,-162.796) B58(-79.96,-161.796) B59(-81.085,-160.796) B60(-79.96,-159.796) B61(-81.085,-158.796) C5(-83.336,-214.796) C6(-82.21,-213.796) C7(-83.336,-212.796) C8(-82.21,-211.796) C9(-83.336,-210.796) C10(-82.21,-209.796) C11(-83.336,-208.796) C12(-82.21,-207.796) C13(-83.336,-206.796) C14(-82.21,-205.796) C15(-83.336,-204.796) C16(-82.21,-203.796) C17(-83.336,-202.796) C18(-82.21,-201.796) C19(-83.336,-200.796) C20(-82.21,-199.796) C21(-83.336,-198.796) C22(-82.21,-197.796) C23(-83.336,-196.796) C24(-82.21,-195.796) C25(-83.336,-194.796) C26(-82.21,-193.796) C27(-83.336,-192.796) C28(-82.21,-191.796) C29(-83.336,-190.796) C30(-82.21,-189.796) C31(-83.336,-188.796) C32(-82.21,-187.796) C33(-83.336,-186.796) C34(-82.21,-185.796) C35(-83.336,-184.796) C36(-82.21,-183.796) C37(-83.336,-182.796) C38(-82.21,-181.796) C39(-83.336,-180.796) C40(-82.21,-179.796) C41(-83.336,-178.796) C42(-82.21,-177.796) C43(-83.336,-176.796) C44(-82.21,-175.796) C45(-83.336,-174.796) C46(-82.21,-173.796) C47(-83.336,-172.796) C48(-82.21,-171.796) C49(-83.336,-170.796) C50(-82.21,-169.796) C51(-83.336,-168.796) C52(-82.21,-167.796) C53(-83.336,-166.796) C54(-82.21,-165.796) C55(-83.336,-164.796) C56(-82.21,-163.796) C57(-83.336,-162.796) C58(-82.21,-161.796) C59(-83.336,-160.796) C60(-82.21,-159.796) C61(-83.336,-158.796) D5(-85.586,-214.796) D6(-84.461,-213.796) D7(-85.586,-212.796) D8(-84.461,-211.796) D9(-85.586,-210.796) D10(-84.461,-209.796) D11(-85.586,-208.796) D12(-84.461,-207.796) D13(-85.586,-206.796) D14(-84.461,-205.796) D15(-85.586,-204.796) D16(-84.461,-203.796) D17(-85.586,-202.796) D18(-84.461,-201.796) D19(-85.586,-200.796) D20(-84.461,-199.796) D21(-85.586,-198.796) D22(-84.461,-197.796) D23(-85.586,-196.796) D24(-84.461,-195.796) D25(-85.586,-194.796) D26(-84.461,-193.796) D27(-85.586,-192.796) D28(-84.461,-191.796) D29(-85.586,-190.796) D30(-84.461,-189.796) D31(-85.586,-188.796) D32(-84.461,-187.796) D33(-85.586,-186.796) D34(-84.461,-185.796) D35(-85.586,-184.796) D36(-84.461,-183.796) D37(-85.586,-182.796) D38(-84.461,-181.796) D39(-85.586,-180.796) D40(-84.461,-179.796) D41(-85.586,-178.796) D42(-84.461,-177.796) D43(-85.586,-176.796) D44(-84.461,-175.796) D45(-85.586,-174.796) D46(-84.461,-173.796) D47(-85.586,-172.796) D48(-84.461,-171.796) D49(-85.586,-170.796) D50(-84.461,-169.796) D51(-85.586,-168.796) D52(-84.461,-167.796) D53(-85.586,-166.796) D54(-84.461,-165.796) D55(-85.586,-164.796) D56(-84.461,-163.796) D57(-85.586,-162.796) D58(-84.461,-161.796) D59(-85.586,-160.796) D60(-84.461,-159.796) D61(-85.586,-158.796) E5(-87.835,-214.796) E6(-86.711,-213.796) E7(-87.835,-212.796) E8(-86.711,-211.796) E9(-87.835,-210.796) E10(-86.711,-209.796) E11(-87.835,-208.796) E12(-86.711,-207.796) E13(-87.835,-206.796) E14(-86.711,-205.796) E15(-87.835,-204.796) E16(-86.711,-203.796) E17(-87.835,-202.796) E18(-86.711,-201.796) E19(-87.835,-200.796) E20(-86.711,-199.796) E21(-87.835,-198.796) E22(-86.711,-197.796) E23(-87.835,-196.796) E24(-86.711,-195.796) E25(-87.835,-194.796) E26(-86.711,-193.796) E27(-87.835,-192.796) E28(-86.711,-191.796) E29(-87.835,-190.796) E30(-86.711,-189.796) E31(-87.835,-188.796) E32(-86.711,-187.796) E33(-87.835,-186.796) E34(-86.711,-185.796) E35(-87.835,-184.796) E36(-86.711,-183.796) E37(-87.835,-182.796) E38(-86.711,-181.796) E39(-87.835,-180.796) E40(-86.711,-179.796) E41(-87.835,-178.796) E42(-86.711,-177.796) E43(-87.835,-176.796) E44(-86.711,-175.796) E45(-87.835,-174.796) E46(-86.711,-173.796) E47(-87.835,-172.796) E48(-86.711,-171.796) E49(-87.835,-170.796) E50(-86.711,-169.796) E51(-87.835,-168.796) E52(-86.711,-167.796) E53(-87.835,-166.796) E54(-86.711,-165.796) E55(-87.835,-164.796) E56(-86.711,-163.796) E57(-87.835,-162.796) E58(-86.711,-161.796) E59(-87.835,-160.796) E60(-86.711,-159.796) E61(-87.835,-158.796) F5(-90.085,-214.796) F6(-88.96,-213.796) F7(-90.085,-212.796) F8(-88.96,-211.796) F9(-90.085,-210.796) F10(-88.96,-209.796) F11(-90.085,-208.796) F12(-88.96,-207.796) F13(-90.085,-206.796) F14(-88.96,-205.796) F15(-90.085,-204.796) F16(-88.96,-203.796) F17(-90.085,-202.796) F18(-88.96,-201.796) F19(-90.085,-200.796) F20(-88.96,-199.796) F21(-90.085,-198.796) F22(-88.96,-197.796) F23(-90.085,-196.796) F24(-88.96,-195.796) F25(-90.085,-194.796) F26(-88.96,-193.796) F27(-90.085,-192.796) F28(-88.96,-191.796) F29(-90.085,-190.796) F30(-88.96,-189.796) F31(-90.085,-188.796) F32(-88.96,-187.796) F33(-90.085,-186.796) F34(-88.96,-185.796) F35(-90.085,-184.796) F36(-88.96,-183.796) F37(-90.085,-182.796) F38(-88.96,-181.796) F39(-90.085,-180.796) F40(-88.96,-179.796) F41(-90.085,-178.796) F42(-88.96,-177.796) F43(-90.085,-176.796) F44(-88.96,-175.796) F45(-90.085,-174.796) F46(-88.96,-173.796) F47(-90.085,-172.796) F48(-88.96,-171.796) F49(-90.085,-170.796) F50(-88.96,-169.796) F51(-90.085,-168.796) F52(-88.96,-167.796) F53(-90.085,-166.796) F54(-88.96,-165.796) F55(-90.085,-164.796) F56(-88.96,-163.796) F57(-90.085,-162.796) F58(-88.96,-161.796) F59(-90.085,-160.796) F60(-88.96,-159.796) F61(-90.085,-158.796) Z5(-76.586,-214.796) Z7(-76.586,-212.796) Z9(-76.586,-210.796) Z11(-76.586,-208.796) Z13(-76.586,-206.796) Z15(-76.586,-204.796) Z17(-76.586,-202.796) Z19(-76.586,-200.796) Z21(-76.586,-198.796) Z23(-76.586,-196.796) Z25(-76.586,-194.796) Z27(-76.586,-192.796) Z29(-76.586,-190.796) Z31(-76.586,-188.796) Z33(-76.586,-186.796) Z35(-76.586,-184.796) Z37(-76.586,-182.796) Z39(-76.586,-180.796) Z41(-76.586,-178.796) Z43(-76.586,-176.796) Z45(-76.586,-174.796) Z47(-76.586,-172.796) Z49(-76.586,-170.796) Z51(-76.586,-168.796) Z53(-76.586,-166.796) Z55(-76.586,-164.796) Z57(-76.586,-162.796) Z59(-76.586,-160.796) Z61(-76.586,-158.796)
PG_LTXDX_F_X1_PG400ND_SL05_V3
  round 0.508 hole 3.2 unplated: (-61.315,154.842)
  round 0.051 hole 2.489x2.21 unplated: (-60.315,220.342)
  rect 1.016x1.016 smd: A1(-65.944,218.796)
  round 1.016 smd: A2(-67.069,217.796) A3(-65.944,216.796) A4(-67.069,215.796) B1(-63.695,218.796) B2(-64.82,217.796) B3(-63.695,216.796) B4(-64.82,215.796) B62(-64.82,157.796) C1(-61.444,218.796) C2(-62.57,217.796) C3(-61.444,216.796) C4(-62.57,215.796) C62(-62.57,157.796) D1(-59.194,218.796) D2(-60.319,217.796) D3(-59.194,216.796) D4(-60.319,215.796) E1(-56.945,218.796) E2(-58.069,217.796) E3(-56.945,216.796) E4(-58.069,215.796) E62(-58.069,157.796) F1(-54.695,218.796) F2(-55.82,217.796) F3(-54.695,216.796) F4(-55.82,215.796) F62(-55.82,157.796) G2(-53.57,217.796) G4(-53.57,215.796) G6(-53.57,213.796) G8(-53.57,211.796) G10(-53.57,209.796) G12(-53.57,207.796) G14(-53.57,205.796) G16(-53.57,203.796) G18(-53.57,201.796) G20(-53.57,199.796) G22(-53.57,197.796) G24(-53.57,195.796) G26(-53.57,193.796) G28(-53.57,191.796) G30(-53.57,189.796) G32(-53.57,187.796) G34(-53.57,185.796) G36(-53.57,183.796) G38(-53.57,181.796) G40(-53.57,179.796) G42(-53.57,177.796) G44(-53.57,175.796) G46(-53.57,173.796) G48(-53.57,171.796) G50(-53.57,169.796) G52(-53.57,167.796) G54(-53.57,165.796) G56(-53.57,163.796) G58(-53.57,161.796) G60(-53.57,159.796)
  custom 0.257x0.257 smd: A5(-65.944,214.796) A6(-67.069,213.796) A7(-65.944,212.796) A8(-67.069,211.796) A9(-65.944,210.796) A10(-67.069,209.796) A11(-65.944,208.796) A12(-67.069,207.796) A13(-65.944,206.796) A14(-67.069,205.796) A15(-65.944,204.796) A16(-67.069,203.796) A17(-65.944,202.796) A18(-67.069,201.796) A19(-65.944,200.796) A20(-67.069,199.796) A21(-65.944,198.796) A22(-67.069,197.796) A23(-65.944,196.796) A24(-67.069,195.796) A25(-65.944,194.796) A26(-67.069,193.796) A27(-65.944,192.796) A28(-67.069,191.796) A29(-65.944,190.796) A30(-67.069,189.796) A31(-65.944,188.796) A32(-67.069,187.796) A33(-65.944,186.796) A34(-67.069,185.796) A35(-65.944,184.796) A36(-67.069,183.796) A37(-65.944,182.796) A38(-67.069,181.796) A39(-65.944,180.796) A40(-67.069,179.796) A41(-65.944,178.796) A42(-67.069,177.796) A43(-65.944,176.796) A44(-67.069,175.796) A45(-65.944,174.796) A46(-67.069,173.796) A47(-65.944,172.796) A48(-67.069,171.796) A49(-65.944,170.796) A50(-67.069,169.796) A51(-65.944,168.796) A52(-67.069,167.796) A53(-65.944,166.796) A54(-67.069,165.796) A55(-65.944,164.796) A56(-67.069,163.796) A57(-65.944,162.796) A58(-67.069,161.796) A59(-65.944,160.796) A60(-67.069,159.796) A61(-65.944,158.796) B5(-63.695,214.796) B6(-64.82,213.796) B7(-63.695,212.796) B8(-64.82,211.796) B9(-63.695,210.796) B10(-64.82,209.796) B11(-63.695,208.796) B12(-64.82,207.796) B13(-63.695,206.796) B14(-64.82,205.796) B15(-63.695,204.796) B16(-64.82,203.796) B17(-63.695,202.796) B18(-64.82,201.796) B19(-63.695,200.796) B20(-64.82,199.796) B21(-63.695,198.796) B22(-64.82,197.796) B23(-63.695,196.796) B24(-64.82,195.796) B25(-63.695,194.796) B26(-64.82,193.796) B27(-63.695,192.796) B28(-64.82,191.796) B29(-63.695,190.796) B30(-64.82,189.796) B31(-63.695,188.796) B32(-64.82,187.796) B33(-63.695,186.796) B34(-64.82,185.796) B35(-63.695,184.796) B36(-64.82,183.796) B37(-63.695,182.796) B38(-64.82,181.796) B39(-63.695,180.796) B40(-64.82,179.796) B41(-63.695,178.796) B42(-64.82,177.796) B43(-63.695,176.796) B44(-64.82,175.796) B45(-63.695,174.796) B46(-64.82,173.796) B47(-63.695,172.796) B48(-64.82,171.796) B49(-63.695,170.796) B50(-64.82,169.796) B51(-63.695,168.796) B52(-64.82,167.796) B53(-63.695,166.796) B54(-64.82,165.796) B55(-63.695,164.796) B56(-64.82,163.796) B57(-63.695,162.796) B58(-64.82,161.796) B59(-63.695,160.796) B60(-64.82,159.796) B61(-63.695,158.796) C5(-61.444,214.796) C6(-62.57,213.796) C7(-61.444,212.796) C8(-62.57,211.796) C9(-61.444,210.796) C10(-62.57,209.796) C11(-61.444,208.796) C12(-62.57,207.796) C13(-61.444,206.796) C14(-62.57,205.796) C15(-61.444,204.796) C16(-62.57,203.796) C17(-61.444,202.796) C18(-62.57,201.796) C19(-61.444,200.796) C20(-62.57,199.796) C21(-61.444,198.796) C22(-62.57,197.796) C23(-61.444,196.796) C24(-62.57,195.796) C25(-61.444,194.796) C26(-62.57,193.796) C27(-61.444,192.796) C28(-62.57,191.796) C29(-61.444,190.796) C30(-62.57,189.796) C31(-61.444,188.796) C32(-62.57,187.796) C33(-61.444,186.796) C34(-62.57,185.796) C35(-61.444,184.796) C36(-62.57,183.796) C37(-61.444,182.796) C38(-62.57,181.796) C39(-61.444,180.796) C40(-62.57,179.796) C41(-61.444,178.796) C42(-62.57,177.796) C43(-61.444,176.796) C44(-62.57,175.796) C45(-61.444,174.796) C46(-62.57,173.796) C47(-61.444,172.796) C48(-62.57,171.796) C49(-61.444,170.796) C50(-62.57,169.796) C51(-61.444,168.796) C52(-62.57,167.796) C53(-61.444,166.796) C54(-62.57,165.796) C55(-61.444,164.796) C56(-62.57,163.796) C57(-61.444,162.796) C58(-62.57,161.796) C59(-61.444,160.796) C60(-62.57,159.796) C61(-61.444,158.796) D5(-59.194,214.796) D6(-60.319,213.796) D7(-59.194,212.796) D8(-60.319,211.796) D9(-59.194,210.796) D10(-60.319,209.796) D11(-59.194,208.796) D12(-60.319,207.796) D13(-59.194,206.796) D14(-60.319,205.796) D15(-59.194,204.796) D16(-60.319,203.796) D17(-59.194,202.796) D18(-60.319,201.796) D19(-59.194,200.796) D20(-60.319,199.796) D21(-59.194,198.796) D22(-60.319,197.796) D23(-59.194,196.796) D24(-60.319,195.796) D25(-59.194,194.796) D26(-60.319,193.796) D27(-59.194,192.796) D28(-60.319,191.796) D29(-59.194,190.796) D30(-60.319,189.796) D31(-59.194,188.796) D32(-60.319,187.796) D33(-59.194,186.796) D34(-60.319,185.796) D35(-59.194,184.796) D36(-60.319,183.796) D37(-59.194,182.796) D38(-60.319,181.796) D39(-59.194,180.796) D40(-60.319,179.796) D41(-59.194,178.796) D42(-60.319,177.796) D43(-59.194,176.796) D44(-60.319,175.796) D45(-59.194,174.796) D46(-60.319,173.796) D47(-59.194,172.796) D48(-60.319,171.796) D49(-59.194,170.796) D50(-60.319,169.796) D51(-59.194,168.796) D52(-60.319,167.796) D53(-59.194,166.796) D54(-60.319,165.796) D55(-59.194,164.796) D56(-60.319,163.796) D57(-59.194,162.796) D58(-60.319,161.796) D59(-59.194,160.796) D60(-60.319,159.796) D61(-59.194,158.796) E5(-56.945,214.796) E6(-58.069,213.796) E7(-56.945,212.796) E8(-58.069,211.796) E9(-56.945,210.796) E10(-58.069,209.796) E11(-56.945,208.796) E12(-58.069,207.796) E13(-56.945,206.796) E14(-58.069,205.796) E15(-56.945,204.796) E16(-58.069,203.796) E17(-56.945,202.796) E18(-58.069,201.796) E19(-56.945,200.796) E20(-58.069,199.796) E21(-56.945,198.796) E22(-58.069,197.796) E23(-56.945,196.796) E24(-58.069,195.796) E25(-56.945,194.796) E26(-58.069,193.796) E27(-56.945,192.796) E28(-58.069,191.796) E29(-56.945,190.796) E30(-58.069,189.796) E31(-56.945,188.796) E32(-58.069,187.796) E33(-56.945,186.796) E34(-58.069,185.796) E35(-56.945,184.796) E36(-58.069,183.796) E37(-56.945,182.796) E38(-58.069,181.796) E39(-56.945,180.796) E40(-58.069,179.796) E41(-56.945,178.796) E42(-58.069,177.796) E43(-56.945,176.796) E44(-58.069,175.796) E45(-56.945,174.796) E46(-58.069,173.796) E47(-56.945,172.796) E48(-58.069,171.796) E49(-56.945,170.796) E50(-58.069,169.796) E51(-56.945,168.796) E52(-58.069,167.796) E53(-56.945,166.796) E54(-58.069,165.796) E55(-56.945,164.796) E56(-58.069,163.796) E57(-56.945,162.796) E58(-58.069,161.796) E59(-56.945,160.796) E60(-58.069,159.796) E61(-56.945,158.796) F5(-54.695,214.796) F6(-55.82,213.796) F7(-54.695,212.796) F8(-55.82,211.796) F9(-54.695,210.796) F10(-55.82,209.796) F11(-54.695,208.796) F12(-55.82,207.796) F13(-54.695,206.796) F14(-55.82,205.796) F15(-54.695,204.796) F16(-55.82,203.796) F17(-54.695,202.796) F18(-55.82,201.796) F19(-54.695,200.796) F20(-55.82,199.796) F21(-54.695,198.796) F22(-55.82,197.796) F23(-54.695,196.796) F24(-55.82,195.796) F25(-54.695,194.796) F26(-55.82,193.796) F27(-54.695,192.796) F28(-55.82,191.796) F29(-54.695,190.796) F30(-55.82,189.796) F31(-54.695,188.796) F32(-55.82,187.796) F33(-54.695,186.796) F34(-55.82,185.796) F35(-54.695,184.796) F36(-55.82,183.796) F37(-54.695,182.796) F38(-55.82,181.796) F39(-54.695,180.796) F40(-55.82,179.796) F41(-54.695,178.796) F42(-55.82,177.796) F43(-54.695,176.796) F44(-55.82,175.796) F45(-54.695,174.796) F46(-55.82,173.796) F47(-54.695,172.796) F48(-55.82,171.796) F49(-54.695,170.796) F50(-55.82,169.796) F51(-54.695,168.796) F52(-55.82,167.796) F53(-54.695,166.796) F54(-55.82,165.796) F55(-54.695,164.796) F56(-55.82,163.796) F57(-54.695,162.796) F58(-55.82,161.796) F59(-54.695,160.796) F60(-55.82,159.796) F61(-54.695,158.796) Z5(-68.194,214.796) Z7(-68.194,212.796) Z9(-68.194,210.796) Z11(-68.194,208.796) Z13(-68.194,206.796) Z15(-68.194,204.796) Z17(-68.194,202.796) Z19(-68.194,200.796) Z21(-68.194,198.796) Z23(-68.194,196.796) Z25(-68.194,194.796) Z27(-68.194,192.796) Z29(-68.194,190.796) Z31(-68.194,188.796) Z33(-68.194,186.796) Z35(-68.194,184.796) Z37(-68.194,182.796) Z39(-68.194,180.796) Z41(-68.194,178.796) Z43(-68.194,176.796) Z45(-68.194,174.796) Z47(-68.194,172.796) Z49(-68.194,170.796) Z51(-68.194,168.796) Z53(-68.194,166.796) Z55(-68.194,164.796) Z57(-68.194,162.796) Z59(-68.194,160.796) Z61(-68.194,158.796)
PG_LTXDX_F_X1_PG400ND_SL11_V3
  round 0.508 hole 3.2 unplated: (11.076,154.842)
  round 0.051 hole 2.489x2.21 unplated: (12.076,220.342)
  rect 1.016x1.016 smd: A1(6.446,218.796)
  round 1.016 smd: A2(5.321,217.796) A3(6.446,216.796) A4(5.321,215.796) B1(8.695,218.796) B2(7.57,217.796) B3(8.695,216.796) B4(7.57,215.796) B62(7.57,157.796) C1(10.946,218.796) C2(9.82,217.796) C3(10.946,216.796) C4(9.82,215.796) C62(9.82,157.796) D1(13.196,218.796) D2(12.071,217.796) D3(13.196,216.796) D4(12.071,215.796) E1(15.445,218.796) E2(14.321,217.796) E3(15.445,216.796) E4(14.321,215.796) E62(14.321,157.796) F1(17.695,218.796) F2(16.57,217.796) F3(17.695,216.796) F4(16.57,215.796) F62(16.57,157.796) G2(18.82,217.796) G4(18.82,215.796) G6(18.82,213.796) G8(18.82,211.796) G10(18.82,209.796) G12(18.82,207.796) G14(18.82,205.796) G16(18.82,203.796) G18(18.82,201.796) G20(18.82,199.796) G22(18.82,197.796) G24(18.82,195.796) G26(18.82,193.796) G28(18.82,191.796) G30(18.82,189.796) G32(18.82,187.796) G34(18.82,185.796) G36(18.82,183.796) G38(18.82,181.796) G40(18.82,179.796) G42(18.82,177.796) G44(18.82,175.796) G46(18.82,173.796) G48(18.82,171.796) G50(18.82,169.796) G52(18.82,167.796) G54(18.82,165.796) G56(18.82,163.796) G58(18.82,161.796) G60(18.82,159.796)
  custom 0.257x0.257 smd: A5(6.446,214.796) A6(5.321,213.796) A7(6.446,212.796) A8(5.321,211.796) A9(6.446,210.796) A10(5.321,209.796) A11(6.446,208.796) A12(5.321,207.796) A13(6.446,206.796) A14(5.321,205.796) A15(6.446,204.796) A16(5.321,203.796) A17(6.446,202.796) A18(5.321,201.796) A19(6.446,200.796) A20(5.321,199.796) A21(6.446,198.796) A22(5.321,197.796) A23(6.446,196.796) A24(5.321,195.796) A25(6.446,194.796) A26(5.321,193.796) A27(6.446,192.796) A28(5.321,191.796) A29(6.446,190.796) A30(5.321,189.796) A31(6.446,188.796) A32(5.321,187.796) A33(6.446,186.796) A34(5.321,185.796) A35(6.446,184.796) A36(5.321,183.796) A37(6.446,182.796) A38(5.321,181.796) A39(6.446,180.796) A40(5.321,179.796) A41(6.446,178.796) A42(5.321,177.796) A43(6.446,176.796) A44(5.321,175.796) A45(6.446,174.796) A46(5.321,173.796) A47(6.446,172.796) A48(5.321,171.796) A49(6.446,170.796) A50(5.321,169.796) A51(6.446,168.796) A52(5.321,167.796) A53(6.446,166.796) A54(5.321,165.796) A55(6.446,164.796) A56(5.321,163.796) A57(6.446,162.796) A58(5.321,161.796) A59(6.446,160.796) A60(5.321,159.796) A61(6.446,158.796) B5(8.695,214.796) B6(7.57,213.796) B7(8.695,212.796) B8(7.57,211.796) B9(8.695,210.796) B10(7.57,209.796) B11(8.695,208.796) B12(7.57,207.796) B13(8.695,206.796) B14(7.57,205.796) B15(8.695,204.796) B16(7.57,203.796) B17(8.695,202.796) B18(7.57,201.796) B19(8.695,200.796) B20(7.57,199.796) B21(8.695,198.796) B22(7.57,197.796) B23(8.695,196.796) B24(7.57,195.796) B25(8.695,194.796) B26(7.57,193.796) B27(8.695,192.796) B28(7.57,191.796) B29(8.695,190.796) B30(7.57,189.796) B31(8.695,188.796) B32(7.57,187.796) B33(8.695,186.796) B34(7.57,185.796) B35(8.695,184.796) B36(7.57,183.796) B37(8.695,182.796) B38(7.57,181.796) B39(8.695,180.796) B40(7.57,179.796) B41(8.695,178.796) B42(7.57,177.796) B43(8.695,176.796) B44(7.57,175.796) B45(8.695,174.796) B46(7.57,173.796) B47(8.695,172.796) B48(7.57,171.796) B49(8.695,170.796) B50(7.57,169.796) B51(8.695,168.796) B52(7.57,167.796) B53(8.695,166.796) B54(7.57,165.796) B55(8.695,164.796) B56(7.57,163.796) B57(8.695,162.796) B58(7.57,161.796) B59(8.695,160.796) B60(7.57,159.796) B61(8.695,158.796) C5(10.946,214.796) C6(9.82,213.796) C7(10.946,212.796) C8(9.82,211.796) C9(10.946,210.796) C10(9.82,209.796) C11(10.946,208.796) C12(9.82,207.796) C13(10.946,206.796) C14(9.82,205.796) C15(10.946,204.796) C16(9.82,203.796) C17(10.946,202.796) C18(9.82,201.796) C19(10.946,200.796) C20(9.82,199.796) C21(10.946,198.796) C22(9.82,197.796) C23(10.946,196.796) C24(9.82,195.796) C25(10.946,194.796) C26(9.82,193.796) C27(10.946,192.796) C28(9.82,191.796) C29(10.946,190.796) C30(9.82,189.796) C31(10.946,188.796) C32(9.82,187.796) C33(10.946,186.796) C34(9.82,185.796) C35(10.946,184.796) C36(9.82,183.796) C37(10.946,182.796) C38(9.82,181.796) C39(10.946,180.796) C40(9.82,179.796) C41(10.946,178.796) C42(9.82,177.796) C43(10.946,176.796) C44(9.82,175.796) C45(10.946,174.796) C46(9.82,173.796) C47(10.946,172.796) C48(9.82,171.796) C49(10.946,170.796) C50(9.82,169.796) C51(10.946,168.796) C52(9.82,167.796) C53(10.946,166.796) C54(9.82,165.796) C55(10.946,164.796) C56(9.82,163.796) C57(10.946,162.796) C58(9.82,161.796) C59(10.946,160.796) C60(9.82,159.796) C61(10.946,158.796) D5(13.196,214.796) D6(12.071,213.796) D7(13.196,212.796) D8(12.071,211.796) D9(13.196,210.796) D10(12.071,209.796) D11(13.196,208.796) D12(12.071,207.796) D13(13.196,206.796) D14(12.071,205.796) D15(13.196,204.796) D16(12.071,203.796) D17(13.196,202.796) D18(12.071,201.796) D19(13.196,200.796) D20(12.071,199.796) D21(13.196,198.796) D22(12.071,197.796) D23(13.196,196.796) D24(12.071,195.796) D25(13.196,194.796) D26(12.071,193.796) D27(13.196,192.796) D28(12.071,191.796) D29(13.196,190.796) D30(12.071,189.796) D31(13.196,188.796) D32(12.071,187.796) D33(13.196,186.796) D34(12.071,185.796) D35(13.196,184.796) D36(12.071,183.796) D37(13.196,182.796) D38(12.071,181.796) D39(13.196,180.796) D40(12.071,179.796) D41(13.196,178.796) D42(12.071,177.796) D43(13.196,176.796) D44(12.071,175.796) D45(13.196,174.796) D46(12.071,173.796) D47(13.196,172.796) D48(12.071,171.796) D49(13.196,170.796) D50(12.071,169.796) D51(13.196,168.796) D52(12.071,167.796) D53(13.196,166.796) D54(12.071,165.796) D55(13.196,164.796) D56(12.071,163.796) D57(13.196,162.796) D58(12.071,161.796) D59(13.196,160.796) D60(12.071,159.796) D61(13.196,158.796) E5(15.445,214.796) E6(14.321,213.796) E7(15.445,212.796) E8(14.321,211.796) E9(15.445,210.796) E10(14.321,209.796) E11(15.445,208.796) E12(14.321,207.796) E13(15.445,206.796) E14(14.321,205.796) E15(15.445,204.796) E16(14.321,203.796) E17(15.445,202.796) E18(14.321,201.796) E19(15.445,200.796) E20(14.321,199.796) E21(15.445,198.796) E22(14.321,197.796) E23(15.445,196.796) E24(14.321,195.796) E25(15.445,194.796) E26(14.321,193.796) E27(15.445,192.796) E28(14.321,191.796) E29(15.445,190.796) E30(14.321,189.796) E31(15.445,188.796) E32(14.321,187.796) E33(15.445,186.796) E34(14.321,185.796) E35(15.445,184.796) E36(14.321,183.796) E37(15.445,182.796) E38(14.321,181.796) E39(15.445,180.796) E40(14.321,179.796) E41(15.445,178.796) E42(14.321,177.796) E43(15.445,176.796) E44(14.321,175.796) E45(15.445,174.796) E46(14.321,173.796) E47(15.445,172.796) E48(14.321,171.796) E49(15.445,170.796) E50(14.321,169.796) E51(15.445,168.796) E52(14.321,167.796) E53(15.445,166.796) E54(14.321,165.796) E55(15.445,164.796) E56(14.321,163.796) E57(15.445,162.796) E58(14.321,161.796) E59(15.445,160.796) E60(14.321,159.796) E61(15.445,158.796) F5(17.695,214.796) F6(16.57,213.796) F7(17.695,212.796) F8(16.57,211.796) F9(17.695,210.796) F10(16.57,209.796) F11(17.695,208.796) F12(16.57,207.796) F13(17.695,206.796) F14(16.57,205.796) F15(17.695,204.796) F16(16.57,203.796) F17(17.695,202.796) F18(16.57,201.796) F19(17.695,200.796) F20(16.57,199.796) F21(17.695,198.796) F22(16.57,197.796) F23(17.695,196.796) F24(16.57,195.796) F25(17.695,194.796) F26(16.57,193.796) F27(17.695,192.796) F28(16.57,191.796) F29(17.695,190.796) F30(16.57,189.796) F31(17.695,188.796) F32(16.57,187.796) F33(17.695,186.796) F34(16.57,185.796) F35(17.695,184.796) F36(16.57,183.796) F37(17.695,182.796) F38(16.57,181.796) F39(17.695,180.796) F40(16.57,179.796) F41(17.695,178.796) F42(16.57,177.796) F43(17.695,176.796) F44(16.57,175.796) F45(17.695,174.796) F46(16.57,173.796) F47(17.695,172.796) F48(16.57,171.796) F49(17.695,170.796) F50(16.57,169.796) F51(17.695,168.796) F52(16.57,167.796) F53(17.695,166.796) F54(16.57,165.796) F55(17.695,164.796) F56(16.57,163.796) F57(17.695,162.796) F58(16.57,161.796) F59(17.695,160.796) F60(16.57,159.796) F61(17.695,158.796) Z5(4.196,214.796) Z7(4.196,212.796) Z9(4.196,210.796) Z11(4.196,208.796) Z13(4.196,206.796) Z15(4.196,204.796) Z17(4.196,202.796) Z19(4.196,200.796) Z21(4.196,198.796) Z23(4.196,196.796) Z25(4.196,194.796) Z27(4.196,192.796) Z29(4.196,190.796) Z31(4.196,188.796) Z33(4.196,186.796) Z35(4.196,184.796) Z37(4.196,182.796) Z39(4.196,180.796) Z41(4.196,178.796) Z43(4.196,176.796) Z45(4.196,174.796) Z47(4.196,172.796) Z49(4.196,170.796) Z51(4.196,168.796) Z53(4.196,166.796) Z55(4.196,164.796) Z57(4.196,162.796) Z59(4.196,160.796) Z61(4.196,158.796)
